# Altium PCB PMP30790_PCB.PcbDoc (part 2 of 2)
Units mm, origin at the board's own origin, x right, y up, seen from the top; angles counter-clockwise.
Board outline 83.5 x 82.5 mm, 4 copper layers (Top Layer, GND, Signal Layer, Bottom Layer), stack 2.155 mm thick; 81 components, 34 nets, 189 pads, 254 vias.
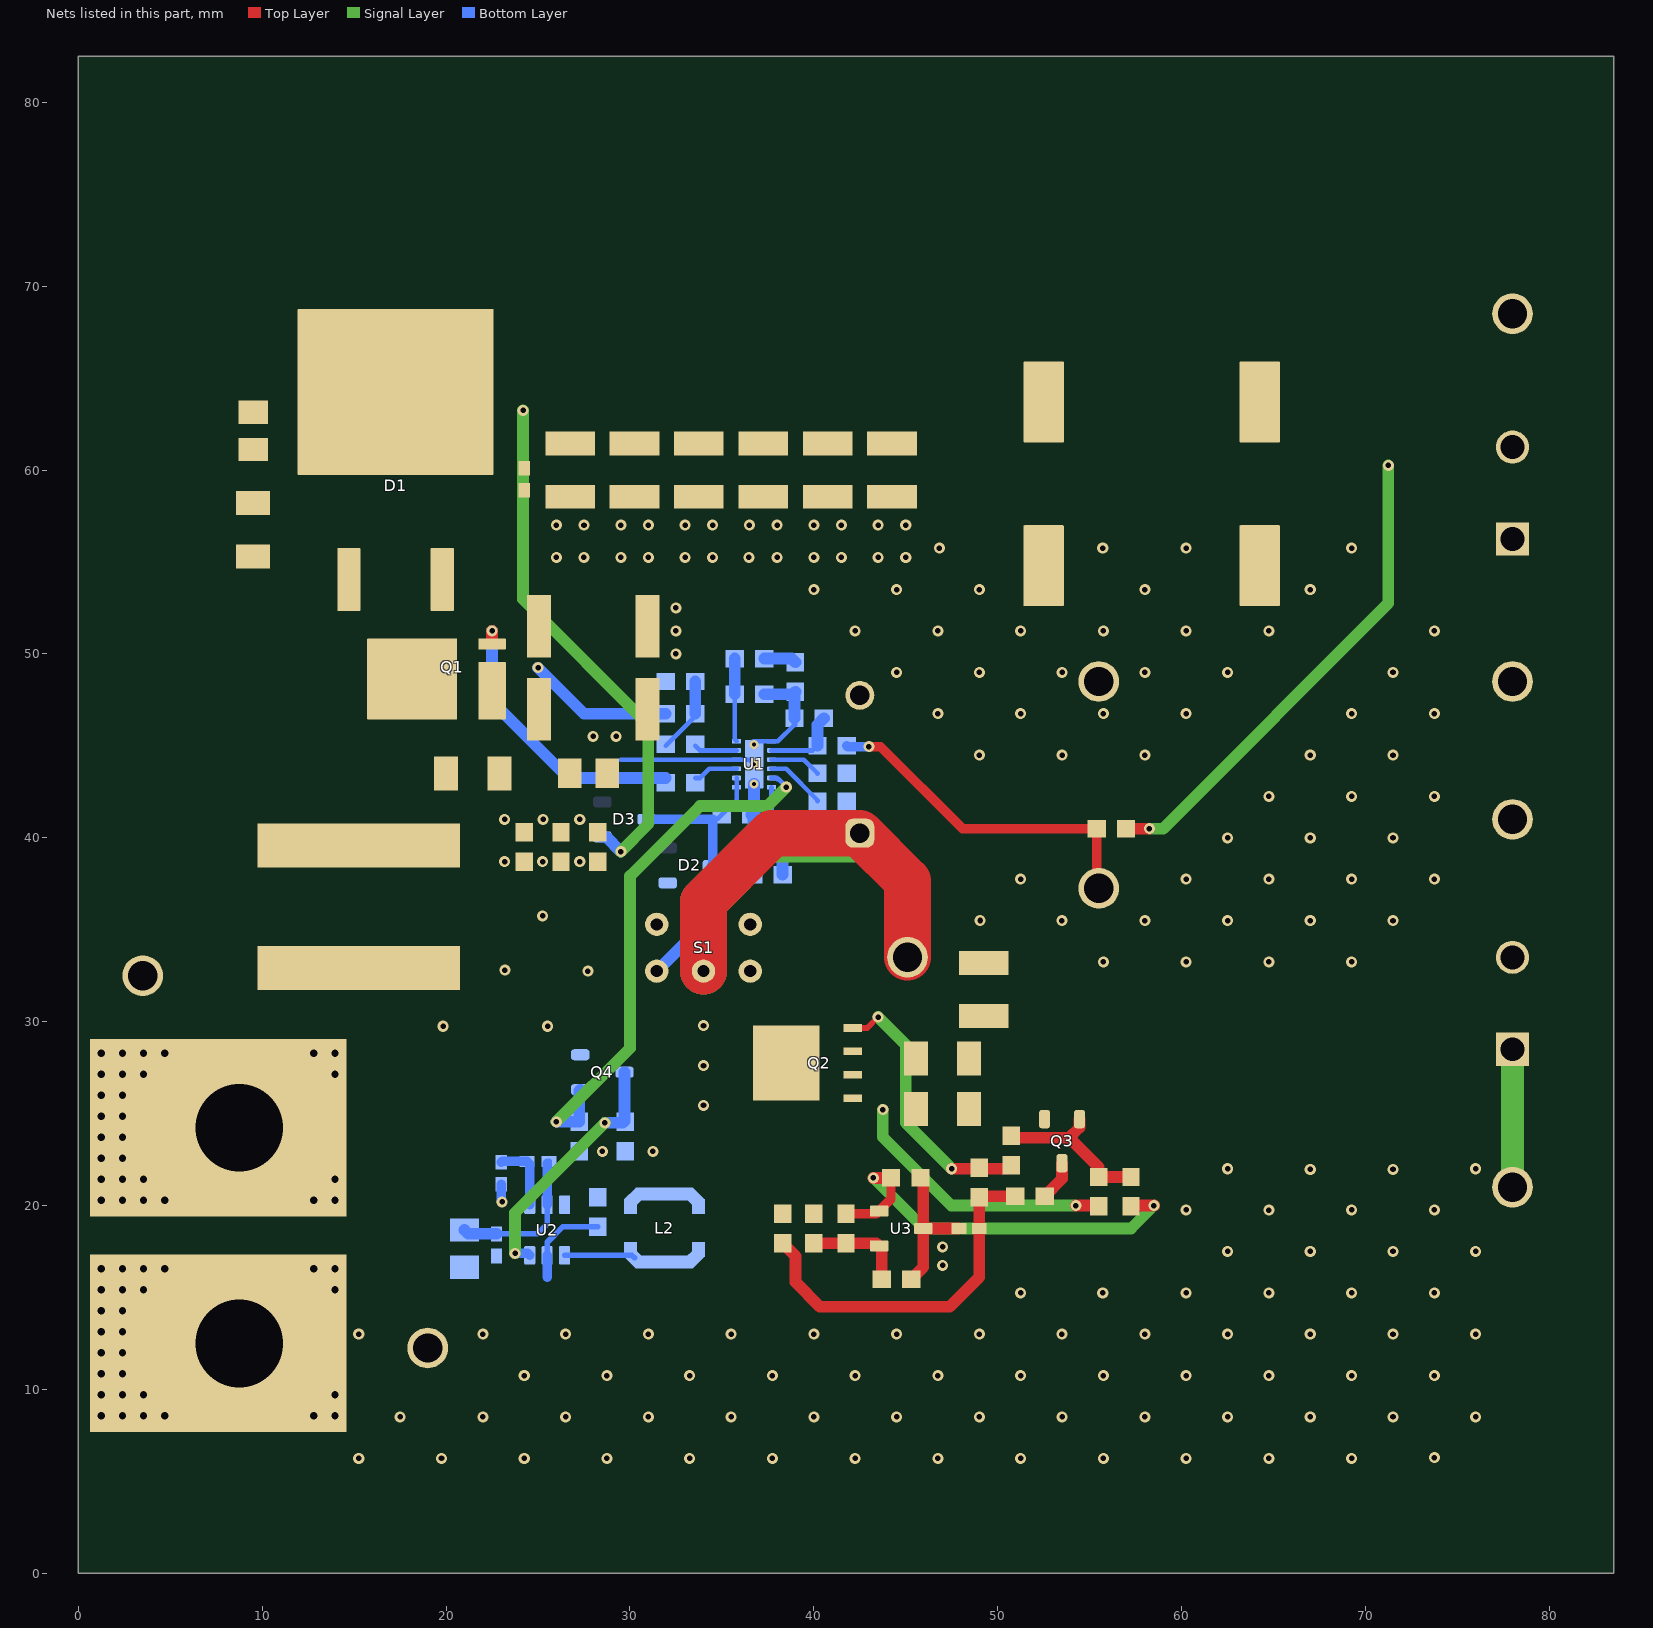
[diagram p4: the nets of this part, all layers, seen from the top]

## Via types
v1: diameter 0.6, hole 0.3, Top Layer to Bottom Layer, 191 vias
v2: diameter 0.813, hole 0.406, Top Layer to Bottom Layer, 56 vias
v3: diameter 5, hole 3, Top Layer to Bottom Layer, 4 vias
v4: diameter 0.5, hole 0.2, Top Layer to Bottom Layer, 3 vias

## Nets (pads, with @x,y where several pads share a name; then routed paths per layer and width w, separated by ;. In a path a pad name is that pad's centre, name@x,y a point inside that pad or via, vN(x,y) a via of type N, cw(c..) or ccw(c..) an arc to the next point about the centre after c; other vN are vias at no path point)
AGND: C2.2 C3.2 C4.2 C5.2 C6.2 C7.2 C8.2 C9.2 C10.2 C11.2 C12.1 C13.1 C14.2 C15.2 C16.2 C17.2 C18.2 C19.2 C20.2 C21.2 C22.2 C23.2 C25.2 C26.2 C27.2 D4.2 J1.1 J2.2 Q4.2 R7.1 R10.1 R11.1 R12.1 R26.1 R27.1 S1.1 S1.3 T2.1 TP3.1 TP4.1 TP6.1 TP9.1 U1.4 U1.7 U1.13@36.75,44 U2.2 U3.3 | length 30.8
  Top Layer w0.635: R26.1@45.3,16 45.95,16.65 U3.3@45.95,18.75 ; C27.2@45.8,21.5 45.95,21.35 U3.3@45.95,18.75 ; D4.2@47.9,18.75 U3.3@45.95,18.75
  Bottom Layer w0.254: 29.5,44.25 U1.4@35.8,44.25 36.5,44.25 v4(36.75,44) ; U1.13@36.7,45.25 U1.7@37.7,45.25 38.05,45.25 R7.1@38.95,46.15
  Bottom Layer w0.305: U2.2@25.5,17.291 25.5,18 26.35,18.85 C23.2@28.25,18.85 ; R7.1@38.95,46.15 R7.1@38.95,46.5
  Bottom Layer w0.508: R27.1@23,21.15 23,20.243 v1(23.05,20.193) ; 25.5,16.093 U2.2@25.5,17.291
  Bottom Layer w0.635: C17.2@36.7,39.5 36.7,41.15 C15.2@36.6,41.25 36.75,41.4 v4(36.75,42.925) ; C20.2@37.3,47.8 38.85,47.8 C21.2@38.95,47.9 ; R7.1@38.95,46.5 C21.2@38.95,47.9 ; C21.2@39,47.95 C21.2@38.95,47.9
  other v1: 15.25,6.25 19.75,6.25 24.25,6.25 28.75,6.25 33.25,6.25 37.75,6.25 42.25,6.25 46.75,6.25 51.25,6.25 55.75,6.25 60.25,6.25 64.75,6.25 69.25,6.25 73.75,6.294 17.5,8.5 22,8.5 26.5,8.5 31,8.5 35.5,8.5 40,8.5 44.5,8.5 49,8.5 53.5,8.5 58,8.5 62.5,8.5 67,8.5 71.5,8.5 76,8.5 24.25,10.75 28.75,10.75 33.25,10.75 37.75,10.75 42.25,10.75 46.75,10.75 51.25,10.75 55.75,10.75 60.25,10.75 64.75,10.75 69.25,10.75 73.75,10.75 15.25,13 22,13 26.5,13 31,13 35.5,13 40,13 44.5,13 49,13 53.489,13 58,13 62.5,13 67,13 71.5,13 76,13 51.25,15.25 55.714,15.25 60.25,15.25 64.75,15.25 69.25,15.25 73.75,15.25 47,16.75 62.5,17.5 67,17.5 71.5,17.5 76,17.5 47,17.75 60.25,19.764 64.75,19.75 69.25,19.764 73.75,19.764 67,21.971 71.5,21.971 62.5,22 76,22 34,25.443 34,27.605 34,29.781 55.75,33.25 60.25,33.25 64.75,33.25 69.25,33.25 49.05,35.502 53.489,35.5 58,35.5 62.5,35.5 67,35.5 71.5,35.5 51.25,37.75 60.25,37.75 64.75,37.75 69.25,37.75 73.75,37.75 62.5,40 67,40 71.5,40 23.188,41 25.276,41 27.269,41 64.75,42.25 69.25,42.25 73.75,42.25 49,44.5 53.5,44.5 58,44.5 67,44.5 71.5,44.5 28,45.516 29.25,45.519 46.75,46.75 51.25,46.75 55.75,46.75 60.25,46.75 69.25,46.75 73.75,46.75 44.5,49 49,49 53.5,49 58,49 62.5,49 71.5,49 32.5,50 32.5,51.25 42.25,51.25 46.75,51.25 51.25,51.25 55.75,51.25 60.25,51.25 64.75,51.25 73.75,51.25 32.5,52.5 40,53.5 44.5,53.5 49,53.5 58,53.5 67,53.5 26,55.25 27.496,55.25 29.5,55.25 31,55.25 33,55.25 34.5,55.25 36.466,55.25 38,55.25 40,55.25 41.5,55.25 43.5,55.25 45,55.25 46.833,55.75 55.714,55.75 60.25,55.75 69.25,55.75 26,57 27.5,57 29.5,57 31,57 33,57 34.5,57 36.5,57 38,57 40,57 41.5,57 43.5,57 45,57
  other v2: 1.257,8.563 2.4,8.563 3.543,8.563 4.686,8.563 12.814,8.563 13.957,8.563 1.257,9.706 2.4,9.706 3.543,9.706 13.957,9.706 1.257,10.849 2.4,10.849 1.257,11.992 2.4,11.992 1.257,13.135 2.4,13.135 1.257,14.278 2.4,14.278 1.257,15.421 2.4,15.421 3.543,15.421 13.957,15.421 1.257,16.564 2.4,16.564 3.543,16.564 4.686,16.564 12.814,16.564 13.957,16.564
  other v4: 36.75,45.075
NetC1_2: C1.2 R1.2
NetC14_1: C14.1 R3.2
NetC15_1: C15.1 D2.3 D3.3 U1.1 U1.2 | length 9.1
  Bottom Layer w0.254: 34.5,41 34.75,41 C15.1@35,41.25 35.8,42.05 U1.1@35.8,42.75 U1.2@35.8,43.25
  Bottom Layer w0.508: D3.3@30.9,41 34.5,41 34.5,38.55 D2.3@34.45,38.5
NetC16_1: C16.1 R8.2 R9.1 | length 4.2
  Bottom Layer w0.254: R8.2@31.95,45 33.55,46.6 R9.1@33.55,46.75
  Bottom Layer w0.635: R9.1@33.55,46.75 C16.1@33.55,48.5
NetC17_1: C17.1 R5.1 U1.12 | length 5
  Bottom Layer w0.254: U1.12@37.7,42.75 37.7,40.1 C17.1@38.3,39.5
  Bottom Layer w0.635: R5.1@38.3,38 C17.1@38.3,39.5
NetC18_1: C18.1 S1.5 TP7.1 | length 35.3
  Top Layer w2.54: S1.5@34,32.75 34,36.524 37.726,40.25 C18.1@42.5,40.25 45.097,37.653 TP7.1@45.097,33.5
  Signal Layer w2.54: S1.5@34,32.75 34,36.524 37.406,39.929 C18.1@42.5,39.929
NetC19_1: C19.1 U1.9 | length 2.8
  Bottom Layer w0.254: U1.9@37.7,44.25 39.45,44.25 C19.1@40.2,43.5
NetC20_1: C20.1 R13.2 U1.6 | length 4.5
  Bottom Layer w0.254: C20.1@35.7,47.8 35.7,45.35 U1.6@35.8,45.25
  Bottom Layer w0.635: C20.1@35.7,47.8 R13.2@35.7,49.75
NetC21_1: C21.1 R13.1 | length 1.8
  Bottom Layer w0.635: R13.1@37.3,49.75 38.8,49.75 C21.1@39,49.55
NetC22_1: C22.1 J2.1 Q3.2 R14.1 R15.1 TP8.1 | length 7.5
  Signal Layer w1.27: TP8.1@78,21 J2.1@78,28.5
NetC24_1: C24.1 C27.1 R20.1 U3.1 | length 23.1
  Top Layer w0.508: C24.1@41.75,19.55 43.4,19.55 U3.1@43.55,19.7 44.2,20.35 C27.1@44.2,21.5
  Top Layer w0.635: v1(43.245,21.5) C27.1@44.2,21.5 ; R20.1@57.25,19.95 57.3,20 v1(58.5,20)
  Signal Layer w0.635: v1(43.245,21.5) 45.995,18.75 57.25,18.75 v1(58.5,20)
NetC24_2: C24.2 R19.1 R26.2 U3.2 | length 5.5
  Top Layer w0.635: R19.1@40,17.95 43.4,17.95 U3.2@43.55,17.8 43.7,17.65 R26.2@43.7,16
NetD1_1: D1.1 D1.3 L1.2 Q1.5-6-7-8 R1.1 R3.1
NetD4_1: D4.1 R18.1 R21.1 R24.2 | length 19.9
  Top Layer w0.635: R18.1@38.3,17.95 39.007,17.242 39.007,15.818 40.326,14.5 47.4,14.5 49,16.1 D4.1@49,18.75 R21.1@49,20.45 49.05,20.5 R24.2@50.95,20.5
NetL2_2: L2.2 U2.1 | length 3.9
  Bottom Layer w0.305: U2.1@26.45,17.291 30.108,17.291 L2.2@30.25,17.149
NetQ1_1-2-3: Q1.1-2-3 R9.2 R10.2 R11.2 | length 8
  Bottom Layer w0.635: v1(25,49.25) 27.5,46.75 R9.2@31.95,46.75
NetQ1_4: Q1.4 R6.2 | length 15.5
  Top Layer w0.635: Q1.4@22.5,50.75 v1(22.5,51.25)
  Bottom Layer w0.635: v1(22.5,51.25) 22.5,47.4 26.65,43.25 R6.2@31.95,43.25
NetQ2_1: Q2.1 Q2.2 Q2.3 R14.2 R15.2 R16.2 | length 14.8
  Top Layer w0.635: v1(54.25,20) 55.45,20 R16.2@55.5,19.95
  Signal Layer w0.635: v1(43.75,25.217) 43.75,23.725 47.475,20 v1(54.25,20)
NetQ2_4: Q2.4 R17.2 R21.2 | length 14.9
  Top Layer w0.305: Q2.4@42.11,29.655 42.905,29.655 v1(43.5,30.25)
  Top Layer w0.635: v1(47.5,22) 50.55,22 R17.2@50.75,22.2
  Signal Layer w0.635: v1(43.5,30.25) 45,28.75 45,24.5 v1(47.5,22)
NetQ2_5: Q2.5 R18.2 R19.2 S1.6
NetQ3_1: Q3.1 R16.1 R17.1 R20.2 | length 9.1
  Top Layer w0.635: R17.1@50.75,23.8 50.75,23.682 53.892,23.682 ; Q3.1@54.45,24.7 54.45,24.241 53.892,23.682 ; R20.2@57.25,21.55 R16.1@55.5,21.55 55.5,22.074 53.892,23.682
NetQ3_3: Q3.3 R24.1 | length 2.2
  Top Layer w0.635: R24.1@52.55,20.5 53.5,21.45 Q3.3@53.5,22.3
NetQ4_3: Q4.3 R22.1 U2.3 | length 13.7
  Signal Layer w0.635: v1(23.75,17.4) 23.75,19.61 v1(28.64,24.5)
  Bottom Layer w0.508: v1(23.75,17.4) 24.441,17.4 U2.3@24.55,17.291
  Bottom Layer w0.635: v1(28.64,24.5) 29.6,24.5 29.7,24.6 Q4.3@29.7,27.25
NetR2_1: R2.1 R4.2 TP5.1 | length 18.7
  Top Layer w0.508: v1(43,44.958) 43.627,44.958 48.085,40.5 R2.1@55.379,40.5 55.379,37.371 TP5.1@55.5,37.25
  Bottom Layer w0.508: R4.2@41.8,45 41.842,44.958 v1(43,44.958)
NetR6_1: R6.1 U1.3 | length 2.5
  Bottom Layer w0.254: R6.1@33.55,43.25 33.807,43.25 34.307,43.75 U1.3@35.8,43.75
NetR8_1: R8.1 U1.5 | length 2.4
  Bottom Layer w0.254: R8.1@33.55,45 33.8,44.75 U1.5@35.8,44.75
NetR12_2: R12.2 U1.10 | length 3.3
  Bottom Layer w0.254: U1.10@37.7,43.75 38.5,43.75 40.2,42.05 R12.2@40.2,42
NetR25_1: R25.1 R27.2 U2.4 | length 3.8
  Bottom Layer w0.508: R27.2@23,22.35 23.05,22.4 R25.1@24.4,22.4 24.55,22.25 U2.4@24.55,20.041
PGOOD: Q4.1 R23.1 U1.11 | length 29.6
  Signal Layer w0.635: v1(26,24.55) 30,28.55 30,37.918 33.807,41.725 37.475,41.725 v1(38.5,42.75)
  Bottom Layer w0.254: U1.11@37.7,43.25 38,43.25 38,43.202 38.056,43.202 38.5,42.758 v1(38.5,42.75)
  Bottom Layer w0.635: v1(26,24.55) R23.1@27.25,24.55 27.25,26.25 Q4.1@27.3,26.3
VAUX: C25.1 C26.1 D2.1 R25.2 U2.5 | length 8.3
  Bottom Layer w0.305: C25.1@22.75,18.456 24.956,18.456 25.5,19 U2.5@25.5,20.041 ; R25.2@25.5,22.3 R25.2@25.6,22.4
  Bottom Layer w0.508: U2.5@25.5,20.041 R25.2@25.5,22.3
  Bottom Layer w0.635: C26.1@21,18.666 21.21,18.456 C25.1@22.75,18.456
VFB: R4.1 R7.2 U1.8 | length 4.2
  Bottom Layer w0.254: U1.8@37.7,44.75 39.95,44.75 R4.1@40.2,45
  Bottom Layer w0.635: R4.1@40.2,45 40.2,46.15 R7.2@40.55,46.5
VIN: C2.1 C3.1 C4.1 C23.1 L1.1 L2.1 R5.2 R22.2 R23.2 S1.4 T1.1 TP1.1 U2.6 | length 7.4
  Bottom Layer w0.635: S1.4@31.46,32.75 36.7,37.99 R5.2@36.7,38
  other v1: 28.5,22.95 31.25,22.95 19.84,29.75 25.52,29.75 27.715,32.75 23.199,32.802 25.25,35.75 23.188,38.7 25.25,38.7 27.269,38.7
  other v2: 1.257,20.288 2.4,20.288 3.543,20.288 4.686,20.288 12.814,20.288 13.957,20.288 1.257,21.431 2.4,21.431 3.543,21.431 13.957,21.431 1.257,22.574 2.4,22.574 1.257,23.717 2.4,23.717 1.257,24.86 2.4,24.86 1.257,26.003 2.4,26.003 1.257,27.146 2.4,27.146 3.543,27.146 13.957,27.146 1.257,28.289 2.4,28.289 3.543,28.289 4.686,28.289 12.814,28.289 13.957,28.289
VOUT: C1.1 C5.1 C6.1 C7.1 C8.1 C9.1 C10.1 C11.1 C12.2 C13.2 D1.2 D3.1 J1.2 R2.2 TP2.1 | length 55.6
  Top Layer w0.635: R2.2@56.979,40.5 v1(58.25,40.5)
  Signal Layer w0.635: v1(24.183,63.25) 24.183,52.967 31,46.15 31,40.75 v1(29.5,39.25) ; v1(58.25,40.5) 59,40.5 71.25,52.75 v1(71.25,60.25)
  Bottom Layer w0.635: D3.1@28.5,40.05 28.7,40.05 v1(29.5,39.25)
pads on no net: D2.2 D3.2 U1.13@36.75,43.315 U1.13@36.75,44.685
copper on no net:
  other v3: 3.75,3.75 79.75,3.75 3.75,78.75 79.75,78.75

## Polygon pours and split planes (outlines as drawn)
AGND on Top Layer "TOP_LAYER_AGND_P022" (solid, remove dead copper, pour order 22): 0.5,82 83,82 83,0.5 0.5,0.5
NetC22_1 on Top Layer "TOP_LAYER_NETC22_1_P020" (solid, remove dead copper, pour order 20): 47.5,30.75 cw(c48,30.75) 48,31.25 82,31.25 cw(c82,30.5) 82.75,30.5 82.75,24.975 cw(c82,24.975) 82,24.225 48.025,24.225 cw(c48.025,24.75) 47.5,24.75
VIN on Top Layer "TOP_LAYER_VIN_P014" (solid, remove dead copper, pour order 14): 0.25,34.75 20.75,34.75 22.5,36.5 22.5,39.25 29.25,39.25 30.5,38 30.495,35.005 32.25,33.25 32.25,21.335 30.165,19.25 0.25,19.25
NetQ2_5 on Top Layer "TOP_LAYER_NETQ2_5_P012" (solid, remove dead copper, pour order 12): 35.75,33 cw(c36.5,33) 36.5,33.75 39.75,33.75 cw(c39.75,33) 40.5,33 40.5,19 36.5,19 cw(c36.5,19.75) 35.75,19.75
NetC14_1 on Top Layer "TOP_LAYER_NETC14_1_P010" (solid, remove dead copper, pour order 10): 22,42 27.5,42 27.5,44.5 22,44.5
NetQ1_1-2-3 on Top Layer "TOP_LAYER_NETQ1_1-2-3_P008" (solid, remove dead copper, pour order 8): 21.75,49.75 23.75,49.75 24.25,50.25 24.25,53.45 26.75,53.45 26.75,45 24.25,45 23.25,46 21.75,46
NetQ2_1 on Top Layer "TOP_LAYER_NETQ2_1_P006" (solid, remove dead copper, pour order 6): 41.242,28 41.242,28.492 cw(c41.75,28.492) 41.75,29 46.25,29 cw(c46.25,28.5) 46.75,28.5 46.75,23.75 cw(c46.25,23.75) 46.25,23.25 41.75,23.25 cw(c41.75,23.75) 41.25,23.75
NetC1_2 on Top Layer "TOP_LAYER_NETC1_2_P004" (solid, remove dead copper, pour order 4): 2.5,60.75 cw(c3.5,60.75) 3.5,61.75 10,61.75 cw(c10,60.75) 11,60.75 10.971,57.971 cw(c10,57.971) 10,57 3.5,57 cw(c3.5,58) 2.5,58
VOUT on Top Layer "TOP_LAYER_VOUT_P002" (solid, remove dead copper, pour order 2): 83,60.5 83,81.25 ccw(c81.999,81.249) 82,82.25 1.75,82 ccw(c1.75,80.75) 0.5,80.75 0.5,63.75 ccw(c1.75,63.75) 1.75,62.5 10.5,62.5 cw(c10.5,61.5) 11.5,61.5 11.5,60.5 ccw(c12.5,60.5) 12.5,59.5 82,59.5 ccw(c82,60.5)
NetD1_1 on Top Layer "TOP_LAYER_NETD1_1_P000" (solid, remove dead copper, pour order 0): 8.25,55.25 cw(c9.25,55.25) 9.25,56.25 20,56.25 cw(c20,55.25) 21,55.25 21,38.5 cw(c20,38.5) 20,37.5 9.25,37.5 cw(c9.25,38.5) 8.25,38.5
AGND on GND "GND_AGND_P016" (solid, remove dead copper, pour order 16): 0.5,82 83,82 83,0.5 0.5,0.5
AGND on Bottom Layer "BOTTOM_LAYER_AGND_P032" (solid, remove dead copper, pour order 32): 0.5,82 83,82 83,0.5 0.5,0.5
VAUX on Bottom Layer "BOTTOM_LAYER_VAUX_P030" (solid, remove dead copper, pour order 30): 22.5,19.5 22.45,19.55 22.45,27.65 30.495,35.695 32.05,37.25 32.05,38 29.75,38 20.25,28.5 20.25,18 24.735,18 26.235,19.5
NetL2_2 on Bottom Layer "BOTTOM_LAYER_NETL2_2_P028" (solid, remove dead copper, pour order 28): 26.5,17.606 29,17.606 ccw(c29.053,18.053) 29.5,18 cw(c30.017,17.983) 30.034,18.5 33.979,18.5 cw(c33.979,18) 34.479,18 34.479,16.479 cw(c34,16.479) 34,16 27,16 cw(c27,16.5) 26.5,16.5
VIN on Bottom Layer "BOTTOM_LAYER_VIN_P024" (solid, remove dead copper, pour order 24): 26,19.494 34.994,19.494 35,19.5 35,23.217 34.467,23.75 26.5,23.75 26,23.25
AGND on Signal Layer "SIGNAL_LAYER_AGND_P036" (solid, remove dead copper, pour order 36): 0.5,82 83,82 83,0.5 0.5,0.5
VIN on Signal Layer "SIGNAL_LAYER_VIN_P034" (solid, remove dead copper, pour order 34): 0.25,34.747 20.75,34.747 22.5,36.497 22.5,39.247 28.975,39.247 28.975,24.192 24.03,19.247 0.25,19.247

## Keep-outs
Keep-Out Layer:
  text ".Layer_Name" at 14.656,-21.806 h1.52

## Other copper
Top Layer:
  pour cut-out: 9.25,34.75 9.25,37.5 21.15,37.5 21.15,35.15 20.75,34.75
  text ".Layer_Name" at 14.656,-21.806 h1.52
GND:
  pour cut-out: 9.25,34.75 9.25,37.5 21.15,37.5 21.15,34.75
Signal Layer:
  pour cut-out: 9.25,34.75 9.25,37.5 21.15,37.5 21.15,35.15 20.75,34.75
Bottom Layer:
  pour cut-out: 9.25,34.75 9.25,37.5 21.15,37.5 21.15,34.75
  pour cut-out: 39.5,49 39.5,46.025 40.11,46.025 40.11,49
  text ".Layer_Name" at 14.656,-21.806 h1.52

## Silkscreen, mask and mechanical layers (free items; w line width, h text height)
Top Overlay:
  text "VOUT" at 76.75,71.75 h1.85
  text "GND" at 76.778,44.25 h1.85
  text "VIN CHARGE" at 61.75,29.434 h1.85
  text "VIN" at 15.75,23.5 h1.85
  text "GND" at 7.25,5.75 h1.85
  text "PMP30790 RevA" at 56.5,2.5 h2.75
  text ".Layer_Name" at 14.656,-21.806 h1.52
Bottom Overlay:
  text ".Layer_Name" at 14.656,-21.806 h1.52
Top Paste:
  text ".Layer_Name" at 14.656,-21.806 h1.52
Bottom Paste:
  text ".Layer_Name" at 14.656,-21.806 h1.52
Top Solder:
  text ".Layer_Name" at 14.656,-21.806 h1.52
  text ".Layer_Name" at 14.656,-21.806 h1.52
Bottom Solder:
  text ".Layer_Name" at 14.656,-21.806 h1.52
Drill Guide:
  text ".Layer_Name" at 14.656,-21.806 h1.52
M1 Board Outline:
  the board outline again, w0.254
  text ".Layer_Name" at 14.656,-21.806 h1.52
M2 Board Dimensions:
  rectangle: 0,-6.985 3.175,-3.81
  rectangle: 3.175,-10.16 12.7,-6.985
  lines w0.178: 0,-6.985 25.4,-6.985 ; 3.175,-10.16 3.175,-3.81 ; 6.35,-10.16 6.35,-3.81 ; 12.7,-10.16 12.7,-3.81 ; 19.05,-10.16 19.05,-3.81 ; 0,-10.16 25.4,-10.16 25.4,-3.81 0,-3.81 0,-10.16
  text ".Layer_Name" at 14.656,-21.806 h1.52
M3 3D STEP Top:
  text ".Layer_Name" at 14.656,-21.806 h1.52
M4 3D STEP Bottom:
  text ".Layer_Name" at 14.656,-21.806 h1.52
M5 Assembly Top:
  lines w0.254: -7.417,-23.626 160.223,-23.626 ; -7.417,-18.462 160.274,-18.462 ; -7.417,-13.297 -7.417,-28.791 94.31,-28.791 160.274,-28.791 160.274,-13.297 -7.404,-13.297 -7.404,-28.791 32.614,-28.791 ; 55.194,-28.791 55.194,-13.297 ; 87.376,-18.462 87.376,-13.297 ; 108.712,-18.462 108.712,-13.297 ; 124.511,-28.956 124.511,-23.804
  text "COMPONENTS MARKED 'DNP' SHOULD NOT BE POPULATED." at 29.299,-8.09 h1.52
  text "ASSEMBLY VARIANT:" at 29.286,-11.024 h1.52
  text ".VariantName" at 55.601,-11.024 h1.52
  text "PCB VIEWED FROM TOP SIDE" at -5.804,-16.654 h1.52
  text "BOARD #:" at 57.099,-16.654 h1.52
  text ".PRJ_Number" at 70.955,-16.654 h1.52
  text "REV:" at 92.405,-16.654 h1.52
  text ".PCB_Rev" at 99.809,-16.654 h1.52
  text "SVN REV:" at 113.69,-16.654 h1.52
  text ".VersionControl_RevNumber" at 126.543,-16.654 h1.52
  text "TID #:" at 57.099,-21.819 h1.52
  text ".TID" at 70.955,-21.819 h1.52
  text "PLOT NAME =" at -5.804,-27.034 h1.52
  text ".plot_File_Name" at 14.656,-27.034 h1.52
  text "GENERATED    :" at 57.15,-27.034 h1.52
  text ".Print_Date" at 79.235,-27.034 h1.52
  text ".Print_Time" at 97.752,-27.034 h1.52
  text "TEXAS INSTRUMENTS" at 129.87,-27.034 h1.52
M6 Assembly Bottom:
  lines w0.254: -7.429,-18.474 160.261,-18.474 ; -7.379,-23.639 160.261,-23.639 ; 28.334,-28.969 28.334,-23.817 ; 44.133,-18.474 44.133,-13.31 ; 65.468,-18.474 65.468,-13.31 ; 97.65,-28.804 97.65,-13.31 ; 120.231,-28.804 160.249,-28.804 160.249,-13.31 -7.429,-13.31 -7.429,-28.804 58.534,-28.804 160.261,-28.804 160.261,-13.31
  text "COMPONENTS MARKED 'DNP' SHOULD NOT BE POPULATED." at 154.991,-8.077 h1.52
  text ".VariantName" at 128.473,-11.024 h1.52
  text "ASSEMBLY VARIANT:" at 154.864,-11.024 h1.52
  text ".VersionControl_RevNumber" at 26.302,-16.667 h1.52
  text "SVN REV:" at 39.154,-16.667 h1.52
  text ".PCB_Rev" at 53.035,-16.667 h1.52
  text "REV:" at 60.439,-16.667 h1.52
  text ".PRJ_Number" at 81.89,-16.667 h1.52
  text "BOARD #:" at 95.745,-16.667 h1.52
  text "PCB VIEWED FROM BOTTOM SIDE" at 158.648,-16.667 h1.52
  text ".TID" at 81.89,-21.831 h1.52
  text "TID #:" at 95.745,-21.831 h1.52
  text "TEXAS INSTRUMENTS" at 22.974,-27.047 h1.52
  text ".Print_Time" at 55.093,-27.047 h1.52
  text ".Print_Date" at 73.609,-27.047 h1.52
  text "GENERATED    :" at 95.694,-27.047 h1.52
  text ".plot_File_Name" at 138.189,-27.047 h1.52
  text "PLOT NAME =" at 158.648,-27.047 h1.52
M9 Title Sheet:
  drawing of 57 lines, arcs and shapes, not listed
  text "1" at 18.792,204.127 h1.78
  text "2" at 82.182,204.127 h1.78
  text "3" at 145.411,204.127 h1.78
  text "4" at 209.08,204.127 h1.78
  text "5" at 272.555,204.127 h1.78
  text "6" at 336.182,204.127 h1.78
  text "A" at -10.579,175.095 h1.78
  text "A" at 365.341,175.095 h1.78
  text "B" at -10.579,114.643 h1.78
  text "B" at 365.341,114.643 h1.78
  text "C" at -10.579,54.318 h1.78
  text "C" at 365.341,54.318 h1.78
  text "PROJECT TITLE:" at 288.125,7.048 h1.14
  text ".PRJ_Title" at 289.395,3.662 h1.78
  text "DESIGNED FOR:" at 288.125,-0.597 h1.14
  text ".PRJ_Customer" at 289.395,-4.153 h1.78
  text "D" at -10.579,-5.88 h1.78
  text "D" at 365.341,-5.88 h1.78
  text "FILE NAME:" at 288.125,-8.217 h1.14
  text ".PCB_File_Name_No_Path" at 289.395,-11.265 h1.78
  text "Texas Instruments (TI) and/or its licensors do not warrant the accuracy or completeness of this specification" at 161.9,-15.376 h1.14
  text "ENGINEER:" at 288.125,-15.583 h1.14
  text "LAYOUT BY:" at 326.352,-15.583 h1.14
  text "or any information contained therein. TI and/or its licensors do not warrant that this design will meet" at 160.757,-18.237 h1.14
  text ".PRJ_Engineer" at 289.395,-19.52 h1.78
  text ".PCB_Layout" at 327.635,-19.52 h1.78
  text "the specifications, will be suitable for your application or fit for any particular purpose, or will operate in" at 160.757,-21.099 h1.14
  text ".Layer_Name" at 14.656,-21.806 h1.52
  text "ALTIUM DESIGNER VERSION:" at 326.352,-23.457 h1.14
  text "an implementation. TI and/or its licensors do not warrant that the design is production worthy. You should" at 160.757,-23.961 h1.14
  text "completely validate and test your design implementation to confirm the system functionality for your application." at 161.9,-26.822 h1.14
  text ".print_Scale" at 289.395,-26.843 h1.78
  text ".Application_BuildNumber" at 327.635,-26.843 h1.78
  text "1" at 18.792,-32.093 h1.78
  text "2" at 82.182,-32.093 h1.78
  text "3" at 145.411,-32.093 h1.78
  text "4" at 209.08,-32.093 h1.78
  text "5" at 272.555,-32.093 h1.78
  text "6" at 336.182,-32.093 h1.78
M10 Fab Notes:
  drawing of 189 lines, arcs and shapes, not listed
  text "DESIGN INFORMATION" at 314.503,161.447 h1.52
  text "MIN. TRACK WIDTH:" at 298.131,158.091 h1.52
  text "8" at 325.976,158.091 h1.52
  text "MIL" at 329.907,158.091 h1.52
  text "MIN. CLEARANCE:" at 298.131,154.938 h1.52
  text "0.2" at 324.452,154.938 h1.52
  text "mm" at 329.907,154.938 h1.52
  text "MIN. VIA PAD SIZE:" at 298.131,151.785 h1.52
  text "24" at 325.214,151.785 h1.52
  text "MIL" at 329.907,151.785 h1.52
  text "0.05mm (2MIL)" at 315.784,148.486 h1.52
  text "MINIMUM ANNULAR RING" at 289.769,148.277 h1.52
  text "EXTERNAL" at 333.768,148.277 h1.52
  text "PER" at 294.849,145.48 h1.52
  text "IPC-D-275 CLASS 2 LEVEL C" at 300.437,145.48 h1.52
  text "MIL, HOLES" at 338.238,142.928 h1.52
  text "+/-" at 328.27,142.709 h1.52
  text "+/-" at 349.961,142.709 h1.52
  text "REGISTRATION TOLERANCES:" at 289.769,142.682 h1.52
  text "METAL" at 320.243,142.682 h1.52
  text "5" at 334.879,142.683 h1.52
  text "3" at 356.037,142.683 h1.52
  text "MIL" at 358.99,142.682 h1.52
  text "HOLE SIZE TOLERANCE (UNLESS OTHERWISE SPECIFIED):" at 289.769,140.185 h1.52
  text "+/-" at 349.961,140.112 h1.52
  text "3" at 356.037,140.085 h1.52
  text "MIL" at 358.99,140.085 h1.52
  text "MATERIAL:" at 287.87,136.589 h1.52
  text "FR-4 High Tg" at 312.926,133.324 h1.52
  text "X" at 309.257,133.122 h1.52
  text "FR-408" at 298.563,133.007 h1.52
  text "OTHER" at 336.358,133.007 h1.52
  text "62 MIL (1.6mm) +/-10%" at 306.694,129.374 h1.52
  text "X" at 303.643,129.312 h1.52
  text "THICKNESS:" at 289.769,129.165 h1.52
  text "OTHER" at 339.33,129.165 h1.52
  text "TOLERANCE:" at 289.769,125.652 h1.52
  text "X" at 311.314,125.652 h1.52
  text "ANSI IPC-6012 TYPE 3 CLASS 2" at 315.836,125.652 h1.52
  text "OTHER +/-" at 315.835,121.989 h1.52
  text "BOW & TWIST:" at 289.769,118.302 h1.52
  text "X" at 311.314,118.302 h1.52
  text "ANSI IPC-6012 TYPE 3 CLASS 2" at 315.836,118.302 h1.52
  text "OTHER +/-" at 315.835,114.576 h1.52
  text "DRILLING:" at 287.87,111.258 h1.52
  text "NC_DRILL FILES" at 332.599,108.586 h1.52
  text "REFERENCE:" at 289.769,108.486 h1.52
  text "X" at 306.463,108.484 h1.52
  text "AS SHOWN" at 310.984,108.486 h1.52
  text "X" at 329.348,108.486 h1.52
  text "OTHER" at 340.168,104.873 h1.52
  text "PTH COPPER THICKNESS:" at 289.761,104.783 h1.52
  text "X" at 318.697,104.783 h1.52
  text "20-30 um" at 321.948,104.783 h1.52
  text "BOARD FINISH:" at 287.87,101.034 h1.52
  text "SILKSCREEN:" at 291.812,98.237 h1.52
  text "X" at 316.14,98.237 h1.52
  text "TOP" at 319.112,98.237 h1.52
  text "X" at 329.094,98.237 h1.52
  text "BOTTOM" at 332.091,98.237 h1.52
  text "SILKSCREEN COLOR:" at 291.812,94.295 h1.52
  text "X" at 316.115,94.295 h1.52
  text "WHITE" at 319.112,94.295 h1.52
  text "OTHER" at 332.091,94.295 h1.52
  text "X" at 319.442,90.652 h1.52
  text "GREEN" at 322.439,90.652 h1.52
  text "OTHER" at 338.136,90.652 h1.52
  text "SOLDER RESIST COLOR:" at 291.812,90.477 h1.52
  text "X" at 319.442,86.734 h1.52
  text "MATTE" at 322.439,86.734 h1.52
  text "SEMI-GLOSS" at 338.125,86.717 h1.52
  text "IMMERSION GOLD (ENIG)" at 314.819,82.345 h1.52
  text "ENEPIG" at 348.793,82.162 h1.52
  text "SURFACE FINISH:" at 287.87,82.136 h1.52
  text "X" at 310.298,82.136 h1.52
  text "IMM. TIN/SILVER OR EQUIV" at 296.24,78.649 h1.52
  text "OTHER" at 332.599,78.549 h1.52
  text "ARRAY/PANEL:" at 287.87,74.602 h1.52
  text "CUT AND TRIM PER M1 BOARD OUTLINE" at 314.819,74.393 h1.52
  text "N.C. ROUTE" at 314.819,70.94 h1.52
  text "X" at 332.295,70.94 h1.52
  text "V. SCORE" at 336.816,70.94 h1.52
  text "CERTIFICATION:" at 287.87,67.66 h1.52
  text "MATERIALS AND WORKMANSHIP FOR ALL PCBS" at 306.285,67.66 h1.52
  text "TO MEET OR EXCEED THE REQUIREMENTS OF:" at 306.285,65.271 h1.52
  text "X" at 297.078,62.003 h1.52
  text "ANSI IPC-A-600F CLASS ->" at 300.329,62.003 h1.52
  text "X" at 342.188,62.003 h1.52
  text "2" at 344.982,62.003 h1.52
  text "1" at 336.981,61.965 h1.52
  text "3" at 353.973,61.965 h1.52
  text "X" at 317.702,58.252 h1.52
  text "RoHS" at 320.953,58.252 h1.52
  text "OTHER" at 337.321,58.252 h1.52
  text "PER ORDER" at 347.407,58.252 h1.52
  text "ALL BOARDS MUST MEET OR EXCEED UL94-V0 REQUIREMENTS." at 288.569,54.345 h1.52
  text "PCB MUST BEAR THE UL94V-0 UL REGISTERED MATERIAL ID NUMBER" at 288.569,51.397 h1.52
  text "ADDITIONAL REQUIREMENTS:" at 287.87,47.094 h1.52
  text "MICROSECTION:" at 289.769,44.373 h1.52
  text "YES" at 312.775,44.373 h1.52
  text "REQUIRED" at 334.657,40.707 h1.52
  text "BARE BOARD ELEC. TEST:" at 289.769,40.634 h1.52
  text "NONE" at 322.935,40.634 h1.52
  text "X" at 331.66,40.634 h1.52
  text "PER ORDER" at 349.693,40.634 h1.52
  text "XX MIL VIAS REQUIRE NON-CONDUCTIVE FILL AND PLANARIZE" at 294.04,35.428 h1.5
  text "XX MIL VIAS REQUIRE CONDUCTIVE FILL AND PLANARIZE" at 294.243,32.787 h1.52
  text "OUTER XX MIL TRACES REQUIRE 50 OHM SINGLE-ENDED IMPEDANCE" at 294.218,28.637 h1.47
  text "LAYER 2 & 3 (INNER LAYERS) XX MIL WIDE, XX MIL SPACE / TRACES REQUIRE 100 OHM DIFFERENTIAL IMPEDANCE" at 294.015,22.65 h1.52
  text ".Layer_Name" at 14.656,-21.806 h1.52
M11 Gerber Information:
  lines w0.254: -7.417,-23.626 160.223,-23.626 ; -7.417,-18.462 160.274,-18.462 ; -7.417,-13.297 -7.417,-28.791 94.31,-28.791 160.274,-28.791 160.274,-13.297 -7.404,-13.297 -7.404,-28.791 32.614,-28.791 ; 55.194,-28.791 55.194,-13.297 ; 87.376,-18.462 87.376,-13.297 ; 108.712,-18.462 108.712,-13.297 ; 124.511,-28.956 124.511,-23.804
  text "ALL ARTWORK VIEWED FROM TOP SIDE" at -5.804,-16.654 h1.52
  text "BOARD #:" at 57.099,-16.654 h1.52
  text ".PRJ_Number" at 70.955,-16.654 h1.52
  text "REV:" at 92.405,-16.654 h1.52
  text ".PCB_Rev" at 99.809,-16.654 h1.52
  text "SVN REV:" at 113.69,-16.654 h1.52
  text ".VersionControl_RevNumber" at 126.543,-16.654 h1.52
  text "LAYER NAME =" at -5.804,-21.806 h1.52
  text "TID #:" at 57.099,-21.819 h1.52
  text ".TID" at 70.955,-21.819 h1.52
  text "PLOT NAME =" at -5.804,-27.034 h1.52
  text ".plot_File_Name" at 14.656,-27.034 h1.52
  text "GENERATED    :" at 57.15,-27.034 h1.52
  text ".Print_Date" at 79.235,-27.034 h1.52
  text ".Print_Time" at 97.752,-27.034 h1.52
  text "TEXAS INSTRUMENTS" at 129.87,-27.034 h1.52
M12 Stackup:
  text ".Layer_Name" at 14.656,-21.806 h1.52
M13 Component Bodies Top:
  text ".Layer_Name" at 14.656,-21.806 h1.52
M14 Component Bodies Bottom:
  text ".Layer_Name" at 14.656,-21.806 h1.52
M15 Courtyards Top:
  text ".Layer_Name" at 14.656,-21.806 h1.52
M16 Courtyards Bottom:
  text ".Layer_Name" at 14.656,-21.806 h1.52
Drill Drawing:
  text ".Layer_Name" at 14.656,-21.806 h1.52
M17 Embedded Cavity:
  text ".Layer_Name" at 14.656,-21.806 h1.52
M18 Embedded Assembly:
  text ".Layer_Name" at 14.656,-21.806 h1.52
M19 Embedded Keepout:
  text ".Layer_Name" at 14.656,-21.806 h1.52

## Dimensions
0,-10.16 to 25.4,-10.16 on M2 Board Dimensions
0,0 to 0,82.5 on M2 Board Dimensions
0,0 to 83.5,0 on M2 Board Dimensions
